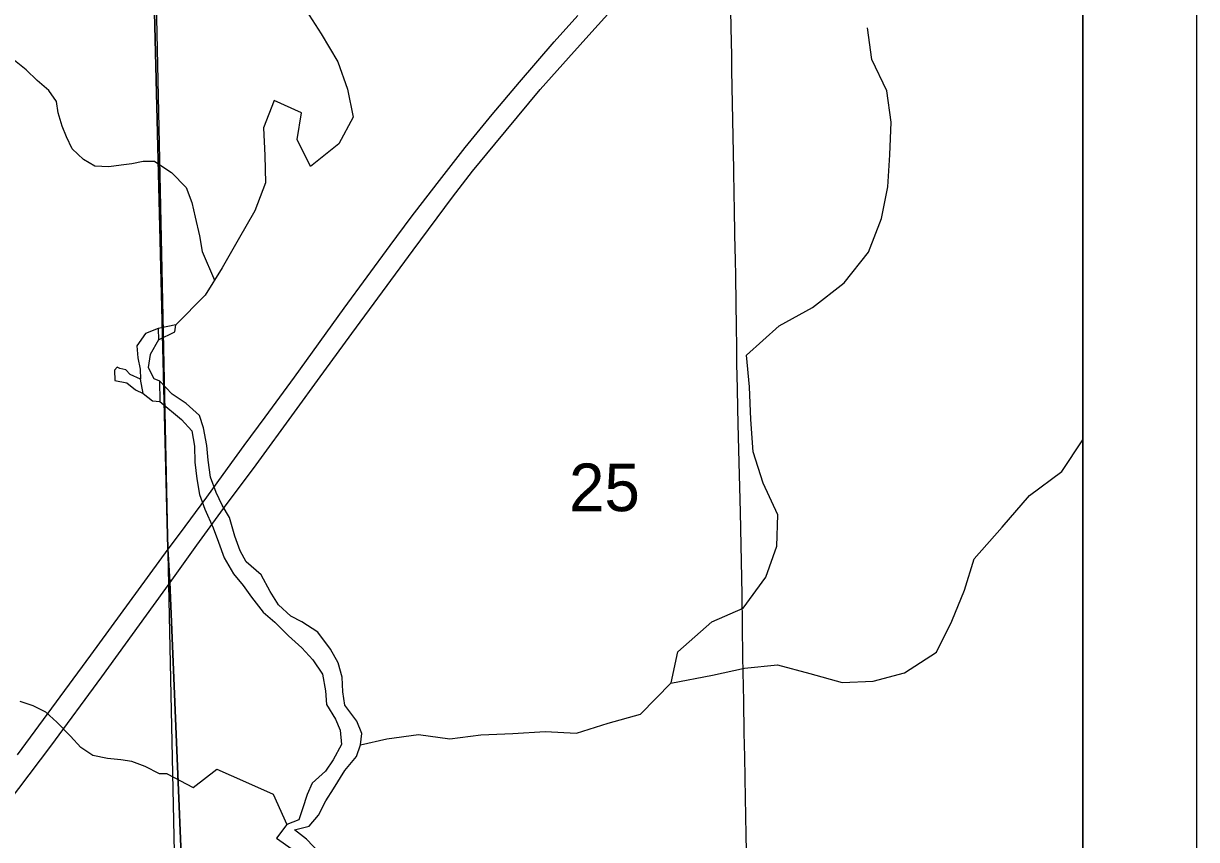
# Model space of a CAD drawing. Extents: x 0 to 34, y 0 to 22.
# Drawn here: x 7.969 to 9, y 18.059 to 18.776 of the extents above; entities that cross this region are included whole.
import ezdxf

# ---------------------------------------------------------------- set-up
doc = ezdxf.new("R2010")
doc.units = 0
for name, color, linetype in [('GM_X_Interstate_Route', 7, 'Continuous'), ('GM_X_Major_River', 7, 'Continuous'), ('GM_X_Minor_River', 7, 'Continuous'), ('GM_X_Section_Text', 7, 'Continuous'), ('GM_X_State_Shield', 7, 'Continuous'), ('GM_X_Township_Road', 7, 'Continuous'), ('SH_Cut_Line', 7, 'Continuous'), ('SH_Data', 7, 'Continuous')]:
    doc.layers.add(name, color=color, linetype=linetype)

msp = doc.modelspace()

# ---------------------------------------------------------------- linework, layer by layer
at = {"layer": 'GM_X_Interstate_Route'}
for points in [[(8.1285, 16.8707), (8.1148, 17.8694), (8.0976, 18.2853), (8.0958, 18.3144), (8.0817, 18.88), (8.0959, 19.2713), (8.1023, 19.3817), (8.0929, 19.6339), (8.0678, 20.8562), (8.0675, 20.8733), (8.067, 20.8954), (8.0669, 20.9), (3.0331, 20.9), (3.0588, 19.9042), (3.067, 19.3838), (3.0747, 18.8969), (3.0724, 18.2926), (3.0939, 16.8719)], [(8.9, 16.8746), (8.9, 20.9), (8.0669, 20.9), (8.067, 20.8954), (8.0675, 20.8733), (8.0678, 20.8562), (8.0929, 19.6339), (8.1023, 19.3817), (8.0959, 19.2713), (8.0817, 18.88), (8.0958, 18.3144), (8.0976, 18.2853), (8.1148, 17.8694), (8.1285, 16.8707)], [(8.0978, 18.2847), (8.1213, 18.3174), (8.1471, 18.353), (8.171, 18.385), (8.2095, 18.4376), (8.2272, 18.4623), (8.2574, 18.5034), (8.3113, 18.5768), (8.346, 18.6231), (8.3636, 18.646), (8.3832, 18.6697), (8.4031, 18.6937), (8.423, 18.7177), (8.448, 18.7457), (8.4685, 18.7685), (8.4937, 18.7965)], [(8.096, 18.3139), (8.1061, 18.3271), (8.13, 18.3597), (8.1481, 18.385), (8.1627, 18.4051), (8.1812, 18.4301), (8.2071, 18.4651), (8.2507, 18.5256), (8.2911, 18.5807), (8.3097, 18.6056), (8.3324, 18.6352), (8.3572, 18.667), (8.3807, 18.696), (8.4048, 18.7244), (8.4353, 18.7596), (8.4561, 18.7827)], [(7.9637, 18.1333), (8.0281, 18.221), (8.096, 18.3139)], [(7.7498, 17.8608), (7.752, 17.8629), (7.7667, 17.8772), (7.7888, 17.899), (7.8128, 17.9234), (7.8319, 17.9437), (7.8526, 17.9668), (7.877, 17.995), (7.8988, 18.0213), (7.9438, 18.0768), (7.9648, 18.1037), (7.9928, 18.141), (8.0377, 18.2019), (8.0978, 18.2847)]]:
    msp.add_lwpolyline(points, dxfattribs=at)
at = {"layer": 'GM_X_Major_River'}
for points in [[(8.2637, 18.8858), (8.2451, 18.8627), (8.2272, 18.8388), (8.2165, 18.8152), (8.2146, 18.7913), (8.2305, 18.7666), (8.2453, 18.7422), (8.2536, 18.7182), (8.2586, 18.6935), (8.246, 18.67), (8.2212, 18.6502), (8.2094, 18.6738), (8.2133, 18.6974), (8.1893, 18.7081), (8.1798, 18.6842), (8.1809, 18.6598), (8.1816, 18.6359), (8.1721, 18.6112), (8.1576, 18.5857), (8.1435, 18.5611), (8.1286, 18.5371), (8.1028, 18.511)], [(8.1028, 18.511), (8.0873, 18.5078)], [(8.0875, 18.498), (8.1018, 18.5049), (8.1028, 18.511)], [(8.0873, 18.5078), (8.0875, 18.498)], [(8.0718, 18.4635), (8.0625, 18.4676), (8.0588, 18.4715), (8.0535, 18.4726), (8.0512, 18.4738), (8.0489, 18.4712), (8.0492, 18.4621), (8.0598, 18.4601), (8.0673, 18.4539), (8.074, 18.4509)], [(8.074, 18.4509), (8.0718, 18.4635)], [(8.0883, 18.4618), (8.0886, 18.4437)], [(8.229, 18.0473), (8.2175, 18.0594), (8.2072, 18.0676), (8.2201, 18.0708), (8.2283, 18.0803), (8.2346, 18.0929), (8.2413, 18.1036), (8.2514, 18.1197), (8.2615, 18.1319), (8.2652, 18.1422), (8.2663, 18.1521), (8.262, 18.163), (8.2512, 18.177), (8.2496, 18.1887), (8.2491, 18.2016), (8.2456, 18.2141), (8.2386, 18.2262), (8.2275, 18.2412), (8.2134, 18.2502), (8.2038, 18.2551), (8.1931, 18.2652), (8.1858, 18.2769), (8.1777, 18.2916), (8.1647, 18.3029), (8.1593, 18.3127), (8.1546, 18.3255), (8.1499, 18.3418), (8.1434, 18.3528), (8.1383, 18.3637), (8.1333, 18.3773), (8.1312, 18.3921), (8.13, 18.405), (8.1272, 18.4205), (8.1236, 18.4315), (8.1118, 18.442), (8.0996, 18.4502), (8.0883, 18.4618)], [(8.0886, 18.4437), (8.1077, 18.4279), (8.1169, 18.4181), (8.1193, 18.4045), (8.1195, 18.3905), (8.1211, 18.3757), (8.1236, 18.362), (8.1282, 18.3492), (8.1356, 18.3329), (8.1403, 18.3201), (8.1453, 18.3065), (8.1534, 18.2925), (8.1619, 18.282), (8.1692, 18.2718), (8.1795, 18.2586), (8.1899, 18.25), (8.2017, 18.238), (8.2136, 18.2274), (8.2232, 18.2169), (8.2316, 18.2041), (8.2344, 18.1897), (8.2353, 18.1776), (8.243, 18.1647), (8.2473, 18.1549), (8.2485, 18.1424), (8.2411, 18.129), (8.2344, 18.1191), (8.2227, 18.1084), (8.2183, 18.0985), (8.2142, 18.0859), (8.2109, 18.0764), (8.2003, 18.0721), (8.1913, 18.0603), (8.2051, 18.0505)]]:
    msp.add_lwpolyline(points, dxfattribs=at)
at = {"layer": 'GM_X_Minor_River'}
for points in [[(8.2652, 18.1422), (8.2883, 18.1475), (8.3162, 18.1513), (8.3435, 18.1475), (8.3709, 18.1509), (8.3991, 18.1521), (8.4273, 18.154), (8.455, 18.1525), (8.4829, 18.1612), (8.5112, 18.1692), (8.5382, 18.1966), (8.5439, 18.2239), (8.5739, 18.2501), (8.6015, 18.2623), (8.6213, 18.2894), (8.6312, 18.3167), (8.632, 18.3441), (8.619, 18.372), (8.6103, 18.3995), (8.6081, 18.428), (8.6069, 18.4566), (8.6043, 18.4844), (8.6332, 18.5102), (8.6623, 18.5262), (8.6904, 18.5479), (8.7117, 18.575), (8.7232, 18.6045), (8.7285, 18.6322), (8.7304, 18.6603), (8.7316, 18.6892), (8.7278, 18.7166), (8.7145, 18.7442), (8.7107, 18.772)], [(8.0844, 18.6546), (8.074, 18.6546), (8.0641, 18.6524), (8.0546, 18.6513), (8.044, 18.6499), (8.0315, 18.6504), (8.0217, 18.6562), (8.0116, 18.6658), (8.0068, 18.6761), (8.003, 18.6856), (7.9994, 18.6974), (7.9979, 18.7073), (7.9912, 18.7168), (7.981, 18.7257), (7.9713, 18.7352), (7.9611, 18.7433)], [(8.0844, 18.6546), (8.0991, 18.6448), (8.112, 18.6318), (8.1169, 18.6185), (8.1199, 18.6056), (8.1237, 18.5892), (8.126, 18.5755), (8.1367, 18.5503)], [(8.0873, 18.5078), (8.0761, 18.5035), (8.0684, 18.4926), (8.0695, 18.482), (8.0713, 18.4721), (8.0718, 18.4635)], [(8.0873, 18.5078), (8.0875, 18.498)], [(8.0875, 18.498), (8.0801, 18.4849), (8.0785, 18.4735), (8.0833, 18.464), (8.0883, 18.4618)], [(8.074, 18.4509), (8.0718, 18.4635)], [(8.0883, 18.4618), (8.0886, 18.4437)], [(8.074, 18.4509), (8.0824, 18.4443), (8.0886, 18.4437)], [(8.5378, 18.1962), (8.5744, 18.2033), (8.6026, 18.2094), (8.6316, 18.2125), (8.66, 18.2049), (8.6884, 18.1969), (8.7158, 18.198), (8.7433, 18.2053), (8.7713, 18.2235), (8.785, 18.2507), (8.7961, 18.278), (8.8045, 18.3056), (8.8292, 18.3334), (8.8532, 18.3613), (8.8816, 18.3822), (8.9, 18.41)], [(8.0952, 18.1168), (8.0883, 18.1168), (8.0759, 18.123), (8.0642, 18.1276), (8.0543, 18.1289), (8.0426, 18.1301), (8.0298, 18.1329), (8.0192, 18.1398), (8.0102, 18.1498), (7.9982, 18.1621), (7.9884, 18.1709), (7.9775, 18.1763), (7.9658, 18.1802)], [(8.0952, 18.1168), (8.1179, 18.1048), (8.1389, 18.1208), (8.164, 18.1097), (8.1883, 18.0987), (8.2003, 18.0721)]]:
    msp.add_lwpolyline(points, dxfattribs=at)
at = {"layer": 'GM_X_State_Shield'}
msp.add_lwpolyline([(8.9, 17.8876), (8.9, 18.8885), (8.0837, 18.878), (8.1051, 17.868)], close=True, dxfattribs=at)
at = {"layer": 'GM_X_Township_Road'}
msp.add_lwpolyline([(8.6047, 18.036), (8.6042, 18.0624), (8.6039, 18.0802), (8.6036, 18.0953), (8.6029, 18.1316), (8.6024, 18.1526), (8.602, 18.1804), (8.6012, 18.2191), (8.6006, 18.2741), (8.5992, 18.3464), (8.5977, 18.4013), (8.5971, 18.424), (8.5969, 18.4378), (8.5965, 18.4553), (8.596, 18.4767), (8.5958, 18.4913), (8.5956, 18.51), (8.5953, 18.5296), (8.595, 18.5544), (8.5947, 18.568), (8.5942, 18.59), (8.5938, 18.6135), (8.5936, 18.6246), (8.5932, 18.6474), (8.5916, 18.7344), (8.5914, 18.7478), (8.5911, 18.7596), (8.5908, 18.7724), (8.5905, 18.7872)], dxfattribs=at)
at = {"layer": 'SH_Cut_Line'}
for points in [[(8.1285, 16.8707), (8.1148, 17.8694), (8.0976, 18.2853), (8.0958, 18.3144), (8.0817, 18.88), (8.0959, 19.2713), (8.1023, 19.3817), (8.0929, 19.6339), (8.0678, 20.8562), (8.0675, 20.8733), (8.067, 20.8954), (8.0669, 20.9), (2.1, 20.9), (2.1, 14.1)], [(8.9, 14.1), (8.9, 20.9), (8.0669, 20.9), (8.067, 20.8954), (8.0675, 20.8733), (8.0678, 20.8562), (8.0929, 19.6339), (8.1023, 19.3817), (8.0959, 19.2713), (8.0817, 18.88), (8.0958, 18.3144), (8.0976, 18.2853), (8.1148, 17.8694), (8.1285, 16.8707)]]:
    msp.add_lwpolyline(points, dxfattribs=at)
at = {"layer": 'SH_Data'}
for p, q in [((9, 21), (9, 14)), ((8.9, 20.9), (8.9, 14.1))]:
    msp.add_line(p, q, dxfattribs=at)

# ---------------------------------------------------------------- texts
at = {"layer": 'GM_X_Section_Text'}
msp.add_text('25', height=0.04186, rotation=0, dxfattribs=at).set_placement((8.4484, 18.3474))

doc.saveas('drawing.dxf')
